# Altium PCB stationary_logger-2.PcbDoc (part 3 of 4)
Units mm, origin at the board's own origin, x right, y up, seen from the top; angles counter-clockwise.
Board outline 105 x 45 mm, 4 copper layers (Top Layer, Layer 2, Layer 3, Bottom Layer), stack 1.492 mm thick; 317 components, 187 nets, 816 pads, 302 vias.
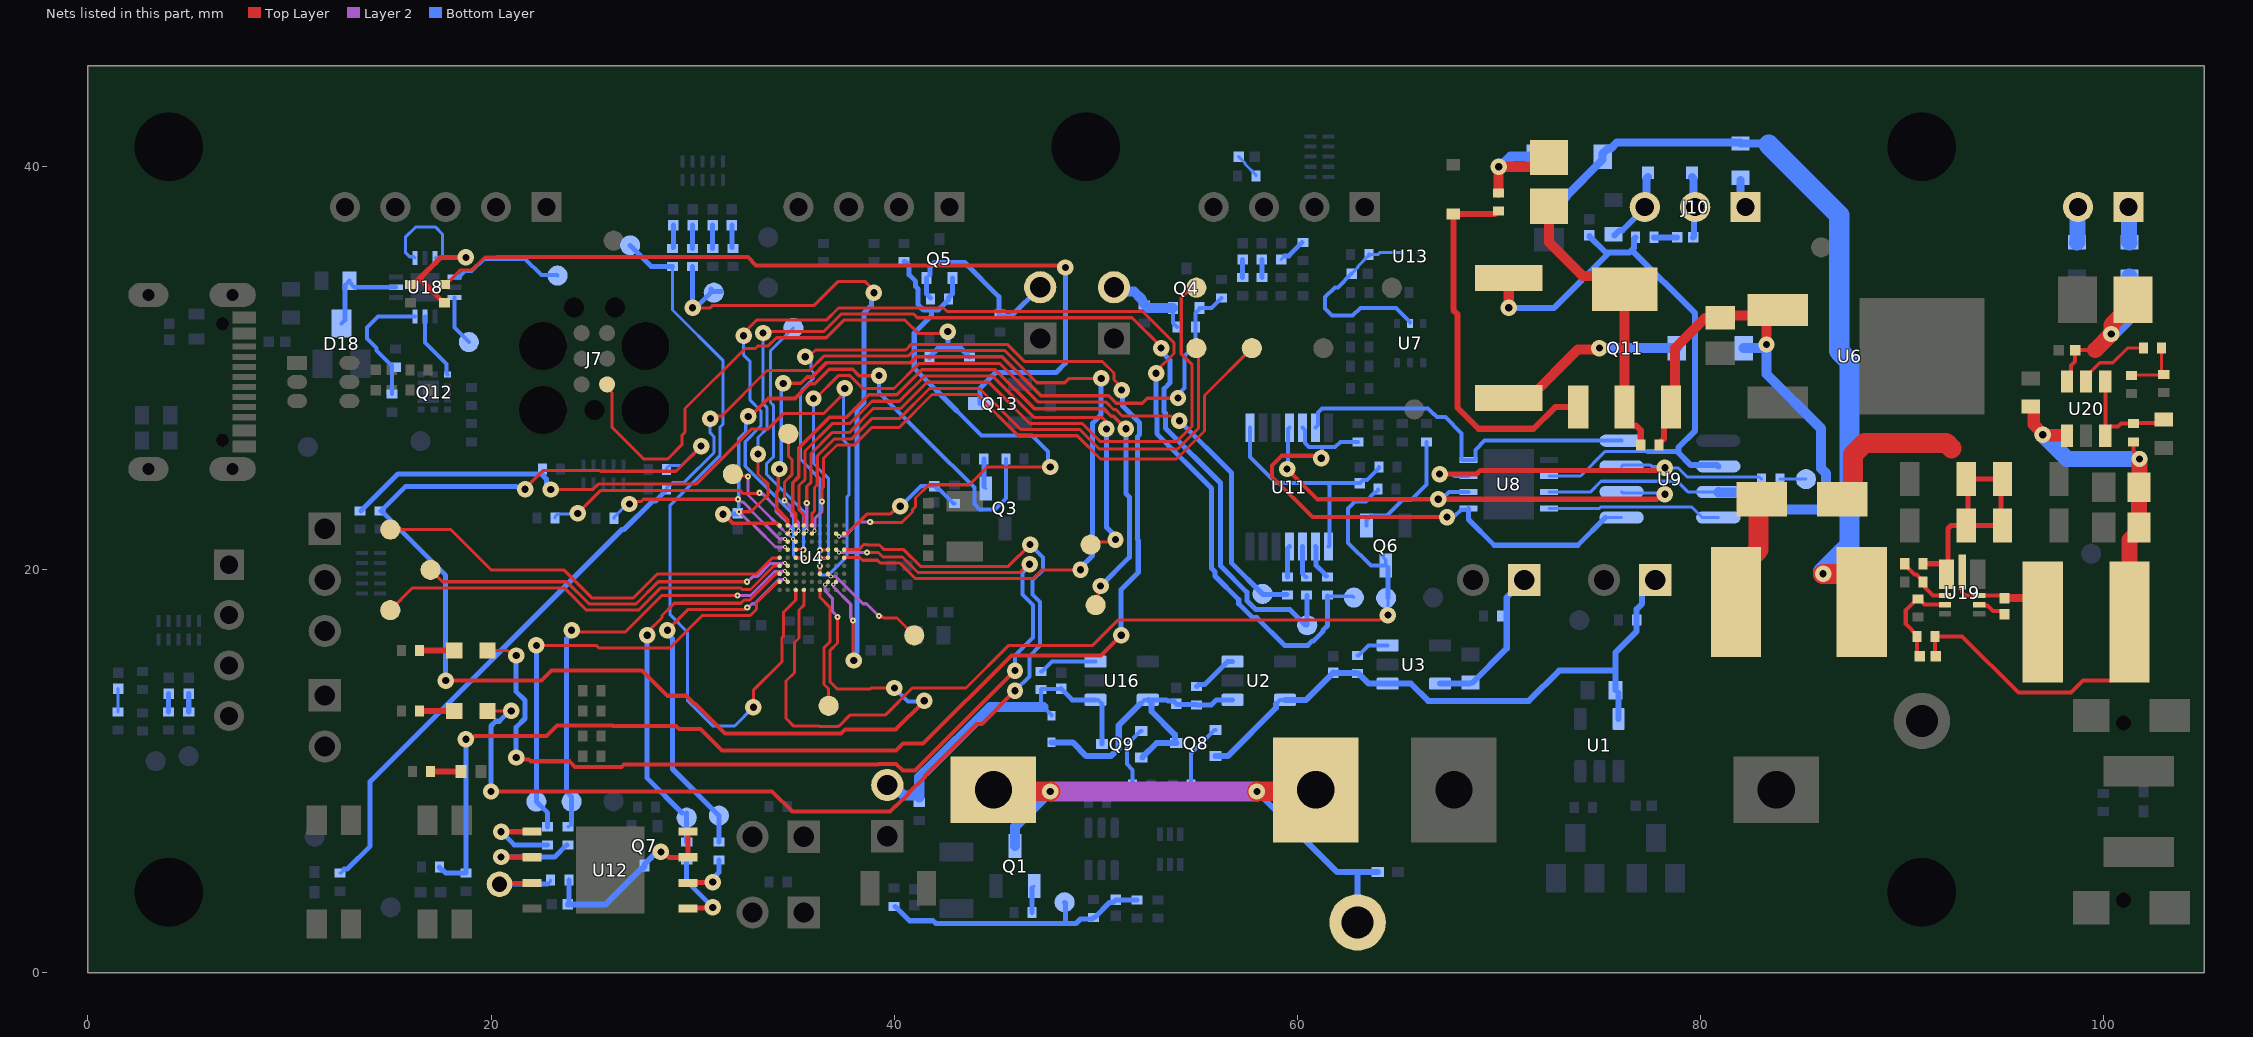
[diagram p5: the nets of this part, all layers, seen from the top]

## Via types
v1: diameter 0.813, hole 0.356, Top Layer to Bottom Layer, tented both sides, 238 vias
v2: diameter 0.305, hole 0.102, Top Layer to Layer 2, tented both sides, 29 vias
v3: diameter 0.203, hole 0.102, Top Layer to Layer 2, tented both sides, 27 vias
v4: diameter 0.305, hole 0.13, Top Layer to Bottom Layer, tented both sides, 8 vias

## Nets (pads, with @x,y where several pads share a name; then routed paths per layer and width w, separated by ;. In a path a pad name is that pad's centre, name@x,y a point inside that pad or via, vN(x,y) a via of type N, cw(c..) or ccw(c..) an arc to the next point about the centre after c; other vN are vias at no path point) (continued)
LED0: D13.A U4.D9 | length 53.3
  Top Layer w0.152: D13.A@19.825,13 v1(21,13) ; U4.D9@37.52,21 38.25,21 38.511,21.26 38.638,21.26 38.663,21.235 39.272,21.235 39.507,21 40.484,21 41.313,20.171 45.671,20.171 v1(46.75,21.25)
  Top Layer w0.2: v1(20,9) 33.947,9 34.947,8 39.796,8 40.064,8.268 40.098,8.268 40.714,8.884 40.714,8.918 41.523,9.727 41.523,9.801 44.081,12.359 44.359,12.359 v1(46,14)
  Bottom Layer w0.2: v1(46,14) 46.708,14.708 46.708,15.708 47.25,16.25 47.25,18.396 46.875,18.772 46.875,19.489 47.386,20 47.386,20.614 v1(46.75,21.25)
  Bottom Layer w0.25: v1(20,9) 20,12.25 20.234,12.484 20.411,12.484 20.927,13 v1(21,13)
LED1: D12.A U4.D8 | length 50.2
  Top Layer w0.152: D12.A@19.825,16 20.821,16 21.071,15.75 v1(21.25,15.75) ; v1(21.25,10.684) v1@21.358,10.576 ; 34.396,10.354 34.401,10.349 ; v2(38.663,20.854) 39.222,20.854 39.365,20.711 39.374,20.711 39.451,20.635 40.418,20.635 41.186,19.867 46.235,19.867 46.642,20.273 v1(46.727,20.273) ; v1@45.756,14.756 v1@45.776,14.756
  Top Layer w0.2: v1@21.358,10.576 21.885,10.576 21.961,10.5 23.893,10.5 24.171,10.223 26.473,10.223 26.599,10.349 34.401,10.349 39.202,10.349 39.226,10.373 40.098,10.373 40.438,10.032 41.032,10.032 v1@45.756,14.756 ; v1@45.776,14.756 46,14.98 v1(46,15)
  Layer 2 w0.152: v3@37.266,20.854 v2(38.663,20.854)
  Bottom Layer w0.2: v1(46,15) 46,15.75 46.885,16.635 46.885,18.263 46.372,18.776 46.372,19.849 46.727,20.205 v1(46.727,20.273)
  Bottom Layer w0.25: v1(21.25,10.684) 21.25,12.188 21.681,12.619 21.681,13.52 21.25,13.951 v1(21.25,15.75)
  other v3: 37.257,20.863
LIN.CS: R86.2 TP25.1 U4.E7 | length 41.2
  Top Layer w0.152: v1(36,28.5) 36.102,28.5 37.237,29.635 37.812,29.635 38.447,29 39.998,29 41.242,30.244 45.233,30.244 47.16,28.317 50.525,28.317 50.891,27.952 50.997,27.952 51.314,27.635 53.74,27.635 53.967,27.409 v1@54.145,27.409 ; v4(36.315,20.586) 36.322,20.593 36.713,20.593 U4.E7@36.72,20.6
  Bottom Layer w0.152: v1(36,28.5) 36,25.27 36.75,24.52 36.75,20.707 36.6,20.556 36.344,20.556 v4(36.315,20.586) ; TP25.1@58.282,18.8 TP25.1@58.307,18.775 ; R86.2@59.49,18.775 R86.2@59.515,18.75
  Bottom Layer w0.25: v1(54.156,27.399) 56.75,24.804 56.75,20.332 TP25.1@58.282,18.8 ; TP25.1@58.307,18.775 R86.2@59.49,18.775
LIN.DATA_IN: R67.2 TP29.1 U4.D2 | length 53.7
  Top Layer w0.152: v2(32.307,22.88) 32.9,22.88 33.306,23.287 33.326,23.287 33.75,23.711 33.75,24.25 33.25,24.75 v1(33.25,25.739) ; v1(33.5,31.75) 33.569,31.819 36.5,31.819 37.371,32.69 40.969,32.69 41.15,32.509 51.806,32.509 53.25,31.065 v1(53.25,31)
  Layer 2 w0.152: v2(32.307,22.88) 32.886,22.302 32.945,22.302 33.159,22.087 34.113,21.133 34.58,21.133 v3(34.583,21.137)
  Bottom Layer w0.152: v1(33.25,25.739) 33.25,26.564 33.703,27.017 33.703,28.034 33.5,28.237 v1(33.5,31.75) ; v1@53.25,30.872 v1(53.25,31) ; R67.2@60.465,18.75 R67.2@60.5,18.715
  Bottom Layer w0.25: v1@53.25,30.872 53.25,30.848 53.684,30.414 53.684,29.269 53.402,28.988 53.402,27.843 53.472,27.773 53.472,27.028 56.195,24.305 56.195,20.199 57.505,18.889 57.505,18.478 57.96,18.023 59.645,18.023 60.418,17.25 TP29.1@60.5,17.25 R67.2@60.5,18.715
LIN.DATA_OUT: R65.2 TP28.1 U4.E3 | length 59.9
  Top Layer w0.152: v1(32.535,31.617) 32.535,31.75 33.17,32.385 36.635,32.385 37.245,32.995 42.451,32.995 42.632,32.813 52.335,32.813 53.885,31.263 53.885,30.737 53,29.852 v1(53,29.75) ; U4.E3@35.12,20.6 35.126,20.594 35.521,20.594 v4(35.527,20.587)
  Bottom Layer w0.152: v1(32.535,31.617) 32.535,30.651 32.858,30.327 32.858,28.418 33.398,27.878 33.398,27.143 32.615,26.36 32.615,25.135 35,22.75 35,20.734 35.146,20.587 v4(35.527,20.587) ; R65.2@61.515,18.687 R65.2@61.515,18.75 61.578,18.687 62.752,18.687 TP28.1@62.815,18.625
  Bottom Layer w0.25: v1(53,29.75) 53,27.676 53.039,27.637 53.039,26.754 55.75,24.042 55.75,20.075 55.924,19.9 55.924,19.696 57.102,18.518 57.102,18.311 57.793,17.62 58,17.62 59.371,16.25 60.53,16.25 60.753,16.473 60.822,16.473 61.277,16.928 61.277,16.997 61.515,17.235 R65.2@61.515,18.687
LIN.nIS_PWRD: Q6.3 R69.2 TP30.1 U4.J4 | length 48.1
  Top Layer w0.152: U4.J4@35.52,19 35.52,18.244 35.285,18.009 35.285,16.617 35.056,16.388 35.056,14.899 34.635,14.478 34.635,12.634 35.029,12.241 36.298,12.241 36.322,12.217 37.178,12.217 37.202,12.24 37.263,12.24 37.827,12.805 39.581,12.805 40.909,14.133 43.571,14.133 45.689,16.25 49.852,16.25 51.102,17.5 64.081,17.5 64.331,17.75 v1(64.5,17.75)
  Bottom Layer w0.152: Q6.3@64.157,20.733 64.398,20.492 Q6.3@64.398,20.209 Q6.3@64.5,20.107 ; v1(64.5,17.75) TP30.1@64.5,18.6
  Bottom Layer w0.2: R69.2@64.009,23.994 64.009,23.944 63.89,23.825 63.84,23.825 63.41,23.395 62.88,23.395 62.526,23.041 62.526,21.34 63.656,20.209 Q6.3@64.398,20.209
  Bottom Layer w0.25: TP30.1@64.5,18.6 Q6.3@64.5,20.107
LIN_BUS: C5.1 R84.2 R85.2 U8.6 U9.6 | length 32.6
  Top Layer w0.5: v1(70.5,33) R84.2@70.5,34.475
  Bottom Layer w0.152: U8.6@72.5,24.65 74.067,24.65 75.294,25.876 77.376,25.876 ; U9.6@80.043,25.192 80.1,25.135 U9.6@80.9,25.135
  Bottom Layer w0.25: 77.376,25.876 78.912,25.876
  Bottom Layer w0.3: v1(70.5,33) 72.75,33 75.5,35.75 ; C5.1@74.5,36.56 74.5,36.55 75.3,35.75 75.5,35.75 ; R85.2@76.8,36.5 76.725,36.425 76.725,35.975 76.612,35.862 ; U9.6@80.9,25.135 80.843,25.192 80.043,25.192 79.54,25.192 78.912,25.821 78.912,25.876 78.912,26.069 79.75,26.907 79.75,32.725 76.612,35.862 ; 75.5,35.75 76.5,35.75 76.612,35.862
LIN_BUSC: D17.2 FB8.2 J10.2 | length 3.1
  Bottom Layer w0.3: FB8.2@79.65,36.5 79.7,36.55 79.7,37.95 J10.2@79.75,38
  Bottom Layer w0.4: D17.2@79.6,39.5 79.675,39.425 79.675,38.075 J10.2@79.75,38
LIN_CSHV: U8.2 U9.2 U11.11 | length 25.4
  Top Layer w0.152: v1@78.071,23.75 v1(78.25,23.75)
  Top Layer w0.2: v1(59.5,25) 61,23.5 v1(67,23.5)
  Top Layer w0.25: v1(67,23.5) 77.821,23.5 v1@78.071,23.75
  Bottom Layer w0.152: v1(67,23.5) v1@67.179,23.5 ; U9.2@76.1,23.865 76.158,23.807 78.193,23.807 v1(78.25,23.75)
  Bottom Layer w0.2: v1(59.5,25) 59.555,25.055 59.555,26.995 U11.11@59.61,27.05 ; v1@67.179,23.5 67.529,23.85 U8.2@68.5,23.85
LIN_RXD: R77.2 U8.1 U9.1 U11.12 | length 27.5
  Top Layer w0.2: v1(61.199,25.538) 61.081,25.655 60.779,25.655 60.775,25.659 59.227,25.659 58.75,25.182 58.75,24.617 60.758,22.609 67.427,22.609 v1(67.434,22.615)
  Bottom Layer w0.152: U9.1@75.3,22.595 U9.1@76.1,22.595
  Bottom Layer w0.2: U11.12@60.26,27.05 60.385,26.925 60.385,26.293 60.58,26.098 61.235,26.098 ; v1(61.199,25.538) 61.235,25.574 61.235,26.098 ; R77.2@63.015,26.35 62.142,26.35 61.89,26.098 61.235,26.098 ; v1(67.434,22.615) 67.461,22.643 67.793,22.643 68.15,23 68.45,23 U8.1@68.5,23.05
  Bottom Layer w0.25: U8.1@68.5,23.05 68.5,22.5 69.781,21.219 73.924,21.219 U9.1@75.3,22.595
LIN_TXD: U8.4 U9.4 U11.13 | length 18.4
  Bottom Layer w0.2: U11.13@60.91,27.05 61.035,27.175 61.035,27.807 61.23,28.002 64.498,28.002 64.5,28 66.5,28 66.773,27.727 66.798,27.727 66.946,27.58 67.352,27.58 68.159,26.773 68.159,25.5 68.209,25.45 U8.4@68.5,25.45 68.8,25.45 68.85,25.5 68.85,25.952 69.303,26.405 U9.4@76.1,26.405
LIN_VBATC: C1.1 D14.A F1.2 FB6.1 | length 39.2
  Top Layer w1: v1(86.1,19.8) 87.275,19.8 88.025,19.05 F1.2@88.025,18.4
  Bottom Layer w0.4: C1.1@72.5,38.125 72.83,38.455 72.88,38.505 73.317,38.505 75.16,40.348 75.16,40.652 75.417,40.91 75.57,40.91 75.86,41.2 FB6.1@82,41.2 ; FB6.1@82,41.15 83.35,41.15
  Bottom Layer w0.5: C1.1@72.83,38.455 73.267,38.455 73.317,38.505
  Bottom Layer w1: 83.4,41.1 86.9,37.6 86.9,30.85 87.4,30.35 87.4,21.2 86.1,19.9 v1(86.1,19.8)
LIN_VBB: C2.1 D16.A Q11.S R76.2 U6.1 U8.7 U9.7 | length 37.4
  Top Layer w0.3: R76.2@77.95,26.2 77.95,26.25 78.2,26.5 78.2,27.725 Q11.S@78.55,28.075 Q11.S@78.75,28.275 ; U6.1@83.29,32.328 83.587,32.625 U6.1@83.85,32.888
  Top Layer w0.5: Q11.S@78.75,28.275 78.75,31 80.25,32.5 C2.1@81,32.5 ; C2.1@81,32.625 U6.1@83.587,32.625 ; v1(83.29,31.181) U6.1@83.29,32.328
  Bottom Layer w0.152: U8.7@72.5,23.85 74.537,23.85 75.081,24.394 78.861,24.394 79.389,23.865 U9.7@80.9,23.865
  Bottom Layer w0.5: U9.7@80.9,23.865 80.919,23.846 81.904,23.846 82.75,23 85.957,23 86.25,23.293 86.25,24.773 86,25.023 86,27 83.29,29.71 v1@83.29,31 ; D16.A@82.16,31 v1@83.29,31 ; v1(83.29,31.181) v1@83.29,31
LIN_WAKEn: R64.1 U8.3 U9.3 | length 20.1
  Top Layer w0.152: v1@78.124,24.935 v1(78.25,25.061)
  Top Layer w0.25: v1(67.068,24.75) 68.903,24.75 69.088,24.935 77.822,24.935 77.841,24.953 78.105,24.953 v1@78.124,24.935
  Bottom Layer w0.152: U9.3@76.1,25.135 76.158,25.192 77.539,25.192 77.615,25.116 78.195,25.116 v1(78.25,25.061) 78.895,25.061 79.35,24.606 82.944,24.606 R64.1@83.05,24.5
  Bottom Layer w0.2: v1(67.068,24.75) 67.703,24.75 67.803,24.65 U8.3@68.5,24.65
M2M_5V_MID: C38.1 C39.1 C40.1 C41.2 L1.2 R100.1 R101.1 U20.1 | length 32
  Top Layer w0.2: C38.1@91.74,15.7 91.65,15.79 R100.1@91.65,16.7 93,16.7 95.8,13.9 98.4,13.9 99,14.5 100.4,14.5 101.3,15.4 L1.2@101.3,17.4 ; R101.1@101.5,26.35 101.5,25.9 101.8,25.6 v1(101.8,25.5)
  Top Layer w0.6: C41.2@96.4,28.1 96.5,28.1 96.55,28.05 96.55,27.208 97,26.758 v1(97,26.7) 97.025,26.675 98.2,26.675 U20.1@98.2,26.65
  Top Layer w0.8: L1.2@101.3,17.4 101.3,21.47 101.775,21.945 C40.1@101.775,22.1 C39.1@101.775,24.1 101.8,24.125 v1(101.8,25.5)
  Bottom Layer w0.8: v1(97,26.7) 98.2,25.5 v1(101.8,25.5)
M2M_5V_OUT: C37.+ C42.2 FB19.1 U20.6 | length 9.2
  Top Layer w0.2: U20.6@98.2,29.35 98.4,29.55 98.4,30.14 98.6,30.34 C42.2@98.6,30.9 99.6,30.9
  Top Layer w0.8: 99.6,30.9 v1(100.4,31.7) 100.4,32.15 101.475,33.225 C37.+@101.475,33.4
  Bottom Layer w0.8: v1(100.4,31.7) 100.4,31.703 101.3,32.603 FB19.1@101.3,34.55
M2M_BST: C28.2 U19.6 | length 1.4
  Top Layer w0.2: U19.6@93.847,18.275 93.882,18.24 94.26,18.24 94.54,17.96 94.94,17.96 C28.2@95.1,17.8
M2M_EN: R99.2 R102.1 U19.2 | length 2.8
  Top Layer w0.2: R99.2@90.15,20.3 90.15,20.25 90.475,19.925 90.479,19.925 90.629,19.775 90.725,19.775 91.05,19.45 R102.1@91.05,19.4 91.05,19.228 91.552,18.725 U19.2@92.152,18.725
M2M_FB: C38.2 R100.2 R104.1 U19.3 | length 4.9
  Top Layer w0.2: C38.2@90.86,15.7 90.75,15.81 R100.2@90.75,16.7 90.75,16.75 90.2,17.3 90.2,18 90.75,18.55 R104.1@90.8,18.55 90.85,18.55 91.125,18.275 U19.3@92.152,18.275
M2M_FLT: C43.2 R101.2 U20.3 U20.4 | length 5.8
  Top Layer w0.2: U20.3@100.1,26.65 U20.3@100.1,26.9 ; U20.4@100.1,29.35 U20.3@100.1,26.9 ; C43.2@103,27.45 102.825,27.275 101.525,27.275 R101.2@101.5,27.25 100.888,27.25 100.737,27.1 100.3,27.1 U20.3@100.1,26.9
M2M_ILIM: R103.1 R105.2 R106.1 | length 3.1
  Top Layer w0.152: R103.1@101.35,29.65 101.375,29.675 102.975,29.675 R106.1@103,29.7 102.9,29.8 R105.2@102.9,31
  Top Layer w0.2: R103.1@101.35,29.65 R103.1@101.4,29.65
MCU_BOOT0: R30.1 R31.1 U4.D7 | length 84.8
  Top Layer w0.152: v1(35.593,30.575) 35.772,30.575 36.102,30.905 40.573,30.905 40.853,31.184 45.623,31.184 46.478,30.328 50.345,30.328 50.91,29.763 50.91,29.434 51.291,29.053 v1(51.291,28.917) ; v4(36.317,20.973) 36.33,20.986 36.706,20.986 U4.D7@36.72,21
  Top Layer w0.2: v1(18.75,11.591) 18.867,11.708 19.132,11.708 19.174,11.75 22.75,11.75 23.277,12.277 26.03,12.277 26.057,12.25 29.171,12.25 29.319,12.102 30.398,12.102 31.47,11.03 40.098,11.03 40.446,11.377 41.446,11.377 45.818,15.75 50.27,15.75 v1(51.27,16.75)
  Bottom Layer w0.152: R31.1@18.7,4.95 R31.1@18.75,4.95 ; v1(35.593,30.575) 35.675,30.575 35.876,30.374 35.876,29.912 36,29.789 36,29.507 35.44,28.947 35.44,28.838 35.365,28.763 35.365,25.474 36.317,24.523 v4(36.317,20.973) ; 52.073,24.176 52.073,24.196
  Bottom Layer w0.25: R30.1@17.45,5.25 17.45,5.2 17.55,5.1 17.6,5.1 17.75,4.95 R31.1@18.7,4.95 ; R31.1@18.75,4.95 v1(18.75,11.591) ; v1(51.27,16.75) 51.27,19.02 52.115,19.865 52.115,21.463 52.073,21.505 52.073,24.176 52.073,26.606 52.184,26.717 52.184,27.283 51.332,28.135 51.332,28.876 v1(51.291,28.917)
MCU_DBG_UART_RX: R35.2 R38.2 U4.H7 | length 65.7
  Top Layer w0.152: v1(17.75,14.5) v1@17.754,14.504 ; v1(21.692,24) 21.692,24.041 22.573,24.922 25.404,24.922 25.435,24.89 29.181,24.89 v1(30.426,26.135) ; v2(37.193,17.654) 37.19,17.651 37.19,16.367 36.83,16.006 36.83,14.434 37.189,14.075 38.795,14.075 38.855,14.135 v1(40.013,14.135)
  Top Layer w0.2: v1@17.754,14.504 22.504,14.504 23,15 27.5,15 28.75,13.75 29.702,13.75 30.102,13.35 30.143,13.35 30.34,13.154 30.346,13.154 31.612,11.888 37.375,11.888 37.569,12.082 40.082,12.082 v1(41.5,13.5)
  Layer 2 w0.152: v3(36.583,19.263) 36.58,19.26 36.58,18.949 36.936,18.593 36.936,17.936 37.193,17.679 v2(37.193,17.654)
  Bottom Layer w0.152: R38.2@14.5,22.928 R38.2@14.55,22.928 ; v1@21.566,24.126 v1(21.692,24) ; R35.2@28.7,24.972 28.7,25.022 28.849,25.171 29.462,25.171 v1(30.426,26.135)
  Bottom Layer w0.2: v1(40.013,14.135) 40.694,13.454 41.454,13.454 v1(41.5,13.5)
  Bottom Layer w0.25: v1(17.75,14.5) 17.75,19.728 14.55,22.928 15.749,24.126 21.265,24.126 21.283,24.108 21.547,24.108 v1@21.566,24.126
MCU_DBG_UART_TX: R36.2 R40.2 U4.G6 | length 38.6
  Top Layer w0.152: v1(22.96,23.983) 22.961,23.982 25.054,23.982 25.322,24.25 30.181,24.25 32.911,26.98 33.732,26.98 34.502,27.75 36.5,27.75 37.374,28.624 37.374,28.646 37.549,28.821 v1(37.549,29) ; v4(36.315,20.181) 36.317,20.178 36.317,19.803 U4.G6@36.32,19.8
  Bottom Layer w0.152: R36.2@13.5,22.928 R36.2@13.55,22.928 ; 22.55,24.7 R40.2@22.55,24.75 ; v4(36.315,20.181) 36.315,19.75 36.75,19.75 37.673,20.673 37.673,23.14 37.673,23.632 37.761,23.72 37.761,26.153 37.5,26.415 37.5,28.951 v1(37.549,29)
  Bottom Layer w0.25: R36.2@13.55,22.928 15.372,24.75 R40.2@22.55,24.75 ; 22.55,24.7 22.755,24.495 22.755,24.145 22.917,23.983 v1(22.96,23.983)
MCU_nRST: R32.1 R42.1 U4.E9 | length 74.8
  Top Layer w0.152: v1(30.883,27.5) 31.01,27.626 31.435,27.626 33.694,29.885 35.801,29.885 36.516,30.6 40.7,30.6 40.979,30.879 45.496,30.879 47.093,29.283 48.473,29.283 48.691,29.5 v1(50.275,29.5) ; U4.E9@37.52,20.6 38.308,20.6 38.435,20.473 39.172,20.473 39.238,20.407 39.248,20.407 39.324,20.33 40.292,20.33 41.06,19.562 46.914,19.562 47.352,20 v1(49.25,20)
  Bottom Layer w0.152: R32.1@12.5,4.95 12.55,4.95 12.699,5.099 R32.1@12.699,5.149 ; R42.1@28.7,23.95 28.7,24.05 28.849,24.199 28.899,24.199 29.041,24.341 29.591,24.341 31.066,25.816 31.066,26.606 30.87,26.801 30.87,27.487 v1(30.883,27.5) ; v1(49.25,20) v1@49.25,20.083
  Bottom Layer w0.25: R32.1@12.699,5.149 12.862,5.149 14,6.286 14,9.5 26.5,22 26.602,22 28.009,23.407 28.157,23.407 R42.1@28.7,23.95 ; v1@49.25,20.083 49.25,20.105 49.851,20.706 49.851,27.278 50.275,27.702 v1(50.275,29.5)
MCU_SPI_FLASH.CIPO: R80.1 TP39.1 U4.G2 | length 21.9
  Top Layer w0.152: v1(24,17) 24.083,16.917 26.667,16.917 28.47,18.72 v2(32.234,18.72)
  Layer 2 w0.152: v2(32.234,18.72) 32.872,18.72 34.066,19.914 34.447,19.914 34.46,19.927 34.574,19.927 v3(34.583,19.937)
  Bottom Layer w0.152: R80.1@23.81,7.25 23.851,7.25 R80.1@24,7.399 ; v1@24,16.831 v1(24,17)
  Bottom Layer w0.25: R80.1@24,7.399 24,8.729 23.75,8.979 23.75,16.581 v1@24,16.831
MCU_SPI_FLASH.COPI: R81.1 TP40.1 U4.G1 | length 19.2
  Top Layer w0.152: v1(27.75,16.75) 27.75,16.895 28.483,17.628 28.483,17.733 29.089,18.339 32.392,18.339 32.556,18.503 32.833,18.503 34.116,19.786 34.306,19.786 U4.G1@34.32,19.8
  Bottom Layer w0.152: TP40.1@29.481,7.929 TP40.1@29.71,7.929
  Bottom Layer w0.25: v1(27.75,16.75) 27.75,9.66 TP40.1@29.481,7.929 ; R81.1@29.71,6.5 TP40.1@29.71,7.929
MCU_SPI_FLASH.nCS: R82.2 TP41.1 U4.H1 | length 22.9
  Top Layer w0.152: v1(22.25,16.25) 25.217,16.25 25.35,16.117 28.863,16.117 30.475,17.73 32.86,17.73 33.177,18.046 33.177,18.365 34.198,19.386 34.306,19.386 U4.H1@34.32,19.4
  Bottom Layer w0.25: v1(22.25,16.25) TP41.1@22.25,8.5 22.81,7.94 R82.2@22.81,7.25
MCU_SPI_FLASH.SCK: R79.1 TP38.1 U4.H2 | length 18.4
  Top Layer w0.152: v1(28.75,17) 29.785,18.035 32.585,18.035 32.672,18.122 v2(32.714,18.122)
  Layer 2 w0.152: v2(32.714,18.122) 32.755,18.122 32.947,18.314 33.075,18.314 34.269,19.508 34.447,19.508 34.466,19.527 34.574,19.527 v3(34.583,19.537)
  Bottom Layer w0.152: v1@28.75,16.831 v1(28.75,17)
  Bottom Layer w0.25: v1@28.75,16.831 29,16.581 29,10.11 TP38.1@31.31,7.8 R79.1@31.31,6.5
MCU_SWCLK: R39.2 U4.B2 | length 13.6
  Top Layer w0.152: v1(24.3,22.8) 25.445,23.945 32.344,23.945 32.496,23.793 33.293,23.793 v2(33.322,23.822) ; U4.B2@34.72,21.8 v3(34.857,21.937)
  Layer 2 w0.152: v2(33.322,23.822) 33.363,23.822 33.435,23.75 33.5,23.75 34.142,23.108 34.142,22.886 34.857,22.171 v3(34.857,21.937)
  Bottom Layer w0.152: R39.2@23.175,22.575 23.175,22.625 23.324,22.774 24.274,22.774 v1(24.3,22.8)
MCU_SWDIO: R37.2 U4.C2 | length 9.7
  Top Layer w0.152: v1(26.867,23.265) 26.994,23.391 27.47,23.391 27.579,23.5 v2(32.25,23.5)
  Layer 2 w0.152: v2(32.25,23.5) 32.291,23.5 32.428,23.363 32.507,23.363 32.847,23.024 32.847,22.988 34.294,21.54 34.58,21.54 v3(34.583,21.537)
  Bottom Layer w0.152: R37.2@26.102,22.56 26.102,22.61 26.757,23.265 v1(26.867,23.265)
nDB: R26.1 R27.2 U18.10 U18.12 | length 11.3
  Top Layer w0.25: R27.2@16,34.05 16.05,34.05 16.4,34.4 ; R26.1@17.7,33.25 17.65,33.25 16.5,34.4 16.4,34.4 ; v1(18.75,35.5) 17.5,35.5 16.4,34.4
  Bottom Layer w0.152: U18.10@16.23,35.47 16.23,35.485 16.181,35.534 15.966,35.534 15.75,35.75 15.75,36.5 16.25,37 17.25,37 17.584,36.666 17.584,35.559 ; U18.12@17.23,35.47 17.279,35.5 v1(18.75,35.5)
NetC4_2: C4.2 D7.A J2.2 Q9.D R3.1 R12.2 U16.1 | length 17.3
  Bottom Layer w0.2: D7.A@47.8,12.76 47.8,12.8 47.291,13.309 R3.1@47.291,14.05 47.316,14.075 48.266,14.075 C4.2@48.291,14.1 ; U16.1@49.991,13.55 50.116,13.55 U16.1@50.316,13.35
  Bottom Layer w0.25: C4.2@48.291,14.1 48.841,13.55 U16.1@49.991,13.55 ; Q9.D@50.316,11.346 U16.1@50.316,13.35
  Bottom Layer w0.5: J2.2@39.662,9.32 39.959,9.32 40.48,8.8 41.15,8.8 41.25,8.7 41.25,9.707 41.543,10 41.575,10 44.766,13.191 47.409,13.191
NetC6_1: C6.1 D18.3 U18.8 | length 4.7
  Bottom Layer w0.2: D18.3@12.58,32.22 D18.3@12.75,32.39 ; C6.1@12.75,34.115 C6.1@12.98,34.345 ; C6.1@12.98,34.27 13.23,34.02 U18.8@15.28,34.02
  Bottom Layer w0.25: D18.3@12.75,32.39 C6.1@12.75,34.115
NetC10_1: C10.1 C14.2 J16.1 Q8.S R1.1 R11.1 U1.5 U2.5 U3.1 | length 30.7
  Bottom Layer w0.2: U2.5@58.95,13.35 59.15,13.55 U2.5@59.4,13.55 ; C14.2@61.8,14.9 C14.2@61.825,14.875 ; R11.1@62.975,14.875 R11.1@63,14.85 R11.1@63.05,14.85 ; C10.1@75.8,14.025 C10.1@75.95,13.875
  Bottom Layer w0.3: Q8.S@55.95,10.75 56.55,10.75 58.95,13.15 U2.5@58.95,13.35 ; U2.5@59.4,13.55 60.45,13.55 C14.2@61.8,14.9 ; C14.2@61.825,14.875 R11.1@62.975,14.875 ; R11.1@63.05,14.85 63.55,14.35 U3.1@64.491,14.35 65.65,14.35 66.5,13.5 71.5,13.5 73,15 75.8,15 ; C10.1@75.8,14.025 75.8,15 ; U1.5@75.95,12.6 C10.1@75.95,13.875 ; J16.1@77.77,19.5 77.12,18.85 77.12,18.32 76.85,18.05 R1.1@76.85,17.5 76.85,16.95 75.8,15.9 75.8,15
NetC13_2: C13.2 D7.K Q8.D Q9.S R10.1 U2.1 U16.5 | length 16.1
  Bottom Layer w0.2: U16.5@52.216,13.35 52.416,13.55 U16.5@52.591,13.55 ; Q9.S@52.266,10.696 Q9.S@52.316,10.696 ; Q8.D@53.95,11.4 Q8.D@54,11.4
  Bottom Layer w0.25: U16.5@52.591,13.55 52.624,13.55 53.516,13.55 53.581,13.485 53.865,13.485 C13.2@54,13.35 54.025,13.325 54.975,13.325 R10.1@55,13.3 55.75,13.3 56,13.55 U2.1@56.8,13.55
  Bottom Layer w0.3: D7.K@47.8,11.44 48.855,11.44 49.545,10.75 50.75,10.75 51.148,11.148 51.148,12.282 U16.5@52.216,13.35 ; Q9.S@52.316,10.696 53.02,11.4 Q8.D@53.95,11.4 ; U16.5@52.624,13.55 52.774,13.4 52.774,12.976 53.933,11.817 53.933,11.467 Q8.D@54,11.4
NetC15_1: C15.1 J3.1 R13.1 U3.5 | length 7.8
  Bottom Layer w0.2: C15.1@68.55,14.35 C15.1@68.6,14.4 C15.1@68.7,14.4
  Bottom Layer w0.3: U3.5@67.091,14.35 C15.1@68.55,14.35 ; C15.1@68.7,14.4 70.4,16.1 70.4,17.7 70.4,18.63 J3.1@71.27,19.5
NetC24_2: C24.2 R29.1 U4.B9 | length 6.8
  Top Layer w0.152: U4.B9@37.52,21.8 37.529,21.809 37.688,21.809 38.638,22.759 39.802,22.759 40.201,23.157 v1(40.302,23.157)
  Bottom Layer w0.2: v1(40.302,23.157) 40.339,23.157 41.332,24.15 C24.2@42,24.15 42.16,23.99 42.26,23.99 42.95,23.3 R29.1@43,23.3
NetC25_2: C25.2 R28.1 U4.A1 | length 28.6
  Top Layer w0.178: v1(31.51,22.76) 31.546,22.76 32.004,22.302 34.205,22.302 34.307,22.2 U4.A1@34.32,22.2 ; v1(32.763,27.615) 32.878,27.615 33.763,28.5 35.084,28.5 35.81,29.226 36.06,29.226 36.787,29.953 37.943,29.953 38.261,29.635 v1(39.25,29.635)
  Bottom Layer w0.178: C25.2@32.225,22.775 C25.2@32.25,22.8 32.297,22.848 32.297,26.492 32.642,26.836 32.642,27.493 v1(32.763,27.615)
  Bottom Layer w0.2: v1(39.25,29.635) 39.25,28.807 41.68,26.377 43.98,24.077 43.98,23.27 44.25,23 45,23 45.55,23.55 R28.1@45.55,25.5
  Bottom Layer w0.25: v1(31.51,22.76) 31.53,22.78 32.22,22.78 C25.2@32.225,22.775
NetC28_1: C28.1 L1.1 U19.7 U19.9 | length 5.8
  Top Layer w0.2: U19.9@93,19.89 93,18.9 93.175,18.725 U19.7@93.847,18.725 94.975,18.725 C28.1@95.1,18.6 ; L1.1@96.1,18.6 97,17.7 L1.1@97,17.4
  Top Layer w0.4: C28.1@95.1,18.6 L1.1@96.1,18.6
NetC29_2: C29.2 R50.2 U7.5 U13.B1 | length 10.3
  Bottom Layer w0.152: C29.2@62.707,34.7 63.018,35.012 63.018,35.062 R50.2@63.557,35.601 ; R50.2@63.557,35.651 64.026,35.651 64.125,35.75 U13.B1@65.207,35.75 ; U7.5@65.607,32.225 U7.5@65.607,32.3
  Bottom Layer w0.2: C29.2@62.707,34.7 62.021,34.015 61.867,34.015 61.377,33.525 61.377,32.975 61.737,32.615 62.756,32.615 63.141,33 64.907,33 U7.5@65.607,32.3 ; R50.2@63.557,35.601 R50.2@63.557,35.651
NetC30_2: C30.2 C31.2 C32.2 C36.2 D10.K R99.1 U19.1 | length 20.2
  Top Layer w0.25: R99.1@91.05,20.3 91.978,20.3 U19.1@92.3,19.978 ; U19.1@92.3,19.822 U19.1@92.3,19.978 ; C31.2@93.275,24.5 94.925,24.5 94.925,22.2 C30.2@93.294,22.2 ; C30.2@93.294,22.182 C30.2@93.294,22.2 ; C31.2@93.294,24.482 C30.2@93.294,22.2 ; U19.1@92.3,19.978 92.3,22.054 92.446,22.2 C30.2@93.294,22.2
  Top Layer w1: D10.K@87.2,23.5 87.575,23.875 87.575,25.714 88.161,26.3 92.2,26.3 92.469,26.031
NetC33_2: C33.2 R63.1 U11.1 U11.8 | length 12
  Bottom Layer w0.2: U11.8@57.66,27.05 57.66,25.59 58.95,24.3 61.5,24.3 ; U11.1@61.56,21.15 61.603,21.193 61.603,24.197 61.5,24.3 ; R63.1@64.065,25.1 64.065,25.05 63.475,24.46 63.27,24.46 C33.2@63.11,24.3 61.5,24.3
NetC35_2: C35.2 Q7.D R78.2 U12.7 U12.8 | length 9.7
  Top Layer w0.25: v1(28.426,6) 28.579,6 28.844,5.735 U12.7@29.78,5.735 U12.8@29.78,7.005
  Bottom Layer w0.152: C35.2@23.81,3.4 C35.2@23.86,3.45 ; Q7.D@27.61,5.325 Q7.D@27.61,5.375
  Bottom Layer w0.25: C35.2@23.86,3.45 R78.2@23.86,4.6
  Bottom Layer w0.3: C35.2@23.81,3.4 25.685,3.4 27.46,5.175 27.51,5.175 27.61,5.275 Q7.D@27.61,5.325 ; Q7.D@27.61,5.375 28.137,5.902 28.328,5.902 v1(28.426,6)
NetD3_2: D3.2 J4.1 Q1.3 TP12.1 | length 29.5
  Top Layer w1: J4.1@44.929,9.08 v1(47.75,9) ; v1(58,9) J4.1@60.929,9.08
  Layer 2 w1: v1@47.83,9 v1(58,9)
  Bottom Layer w0.3: v1(58,9) 62,5 62.975,5 ; TP12.1@63,2.5 63,4.975 62.975,5 ; D3.2@64,5 62.975,5
  Bottom Layer w0.5: Q1.3@46,6.291 46.009,6.3 46.009,7.259 v1(47.75,9)
NetD9_1: D9.1 J7.1 R34.2 | length 26.9
  Top Layer w0.152: J7.1@25.762,29.203 25.762,29.028 26,28.79 26,27.071 27.571,25.5 28.763,25.5 29.486,26.223 29.486,26.69 29.626,26.83 29.626,28.003 32.608,30.985 33.122,30.985 33.25,31.113 33.764,31.113 34.166,31.515 36.627,31.515 37.497,32.385 40.545,32.385 41.198,31.732 42.579,31.732 v1(42.666,31.819)
  Bottom Layer w0.25: D9.1@41.75,30.5 41.75,30.55 42.204,31.004 42.6,31.004 ; v1(42.666,31.819) 42.666,31.07 42.6,31.004 ; R34.2@43.75,30.55 43.296,31.004 42.6,31.004
NetD10_A: D10.A F1.1 | length 5.6
  Top Layer w1: F1.1@81.775,18.4 81.775,19.875 82.9,21 D10.A@82.9,23.5
NetD11_K: D11.K R116.2 | length 1.5
  Top Layer w0.3: R116.2@17,10 D11.K@18.5,10
NetD12_K: D12.K R44.2 | length 1.7
  Top Layer w0.3: R44.2@16.45,16 D12.K@18.175,16
NetD13_K: D13.K R46.2 | length 1.7
  Top Layer w0.3: R46.2@16.45,13 D13.K@18.175,13
NetD14_K: D14.K R74.1 R75.2 | length 6
  Top Layer w0.5: R74.1@70,38.7 v1(70,40) 72.04,40 R75.2@72.5,40.46
  Bottom Layer w0.5: v1(70,40) 70.085,40 70.585,40.5 D14.K@71.84,40.5
NetD15_K: D15.K Q11.G R74.2 | length 18.9
  Top Layer w0.3: R74.2@70,37.8 69.95,37.8 69.808,37.658 D15.K@67.75,37.658 67.75,32.889 67.956,32.683 67.956,28.044 69,27 71.728,27 72.803,28.075 Q11.G@73.95,28.075
NetD16_K: D16.K R84.1 | length 10.4
  Top Layer w0.5: R84.1@69.475,28.525 R84.1@70.5,28.525 71.525,28.525 73.94,30.94 74.94,30.94 v1(75,31)
  Bottom Layer w0.5: v1(75,31) D16.K@78.84,31
NetD17_1: D17.1 FB7.2 J10.3 | length 3.7
  Bottom Layer w0.3: FB7.2@75.75,36.6 75.988,36.838 76.135,36.838 77.25,37.952 J10.3@77.25,38
  Bottom Layer w0.4: J10.3@77.25,38 77.325,38.075 77.325,39.425 D17.1@77.4,39.5
NetFB3_1: FB3.1 R59.2 | length 1.5
  Bottom Layer w0.152: FB3.1@59.2,35.397 FB3.1@59.384,35.581 ; R59.2@60.25,36.247 R59.2@60.3,36.247
  Bottom Layer w0.25: FB3.1@59.384,35.581 59.584,35.581 R59.2@60.25,36.247
NetFB4_1: FB4.1 R61.2 | length 0.9
  Bottom Layer w0.25: R61.2@58.25,34.497 FB4.1@58.25,35.397
NetFB5_1: FB5.1 R62.2 | length 0.9
  Bottom Layer w0.25: R62.2@57.3,34.497 FB5.1@57.3,35.397
NetFB6_2: FB6.2 J10.1 | length 1.5
  Bottom Layer w0.4: FB6.2@82,39.35 82,38.25 J10.1@82.25,38
NetFB8_1: FB8.1 R85.1 | length 1.2
  Bottom Layer w0.3: R85.1@77.7,36.5 FB8.1@78.85,36.5
NetFB11_1: FB11.1 R87.2 | length 1.3
  Bottom Layer w0.152: FB11.1@57.1,40.5 57.411,40.189 57.411,40.138 57.95,39.6 R87.2@57.95,39.55
NetFB12_1: FB12.1 R88.2 | length 1.2
  Bottom Layer w0.152: R88.2@31.95,36 R88.2@32,35.95
  Bottom Layer w0.25: R88.2@31.95,36 FB12.1@31.95,37.1
NetFB13_1: FB13.1 R89.2 | length 1.2
  Bottom Layer w0.25: R89.2@31,35.95 FB13.1@31,37.1
NetFB14_1: FB14.1 R90.2 | length 1.2
  Bottom Layer w0.152: R90.2@1.5,12.95 FB14.1@1.5,14.1
NetFB15_1: FB15.1 R93.2 | length 0.9
  Bottom Layer w0.25: R93.2@4,12.95 FB15.1@4,13.85
NetFB16_1: FB16.1 R94.2 | length 0.9
  Bottom Layer w0.25: R94.2@5,12.95 FB16.1@5,13.85
NetFB17_1: FB17.1 R66.2 | length 1.2
  Bottom Layer w0.25: R66.2@30,35.95 FB17.1@30,37.1
NetFB18_1: FB18.1 R68.2 | length 1.2
  Bottom Layer w0.152: R68.2@29,35.95 R68.2@29.05,36
  Bottom Layer w0.25: R68.2@29.05,36 FB18.1@29.05,37.1
NetFB19_2: FB19.2 J19.1 | length 1.8
  Bottom Layer w0.8: J19.1@101.25,38 101.275,37.975 101.275,36.275 FB19.2@101.3,36.25
NetFB20_2: FB20.2 J19.2 | length 1.8
  Bottom Layer w0.8: FB20.2@98.7,36.25 98.725,36.275 98.725,37.975 J19.2@98.75,38
NetJ9_2: J9.2 Q4.S R45.2 R47.1 | length 4.2
  Bottom Layer w0.2: Q4.S@53.85,32.997 53.85,32.246 R47.1@54.05,32.046
  Bottom Layer w0.5: J9.2@50.912,34.02 51.122,33.81 51.899,33.81 52.312,33.397 ; R45.2@52.4,33.2 52.603,32.997 Q4.S@53.85,32.997
NetJ11_2: J11.2 Q5.S R54.2 R56.1 | length 9.5
  Bottom Layer w0.152: Q5.S@41.6,34.472 Q5.S@41.774,34.646 ; R56.1@41.8,33.447 R56.1@41.8,33.497
  Bottom Layer w0.25: Q5.S@41.6,34.472 41.6,33.697 R56.1@41.8,33.497 ; Q5.S@41.774,34.646 41.774,35.024 42,35.25 43.5,35.25 45.2,33.55 45.2,32.6 45.83,32.6 J11.2@47.25,34.02
NetQ1_1: Q1.1 R14.1 | length 1.4
  Bottom Layer w0.152: Q1.1@46.85,4.209 Q1.1@46.95,4.309
  Bottom Layer w0.25: R14.1@46.85,3 Q1.1@46.85,4.209
NetQ3_1: Q3.1 R25.2 | length 1.5
  Bottom Layer w0.152: Q3.1@44.45,24.133 Q3.1@44.55,24.033
  Bottom Layer w0.25: Q3.1@44.45,24.133 R25.2@44.45,25.5
NetQ6_1: Q6.1 R70.1 | length 6.1
  Bottom Layer w0.2: Q6.1@63.448,22.191 63.448,22.473 63.665,22.691 64.463,22.691 65.231,23.459 65.641,23.459 66.409,24.227 66.409,26.34 R70.1@66.419,26.35
NetQ8_G: Q8.G R2.1 | length 3.3
  Bottom Layer w0.2: R2.1@54.741,9.316 54.741,10.891 55.9,12.05 Q8.G@55.95,12.05
NetQ9_G: Q9.G R118.1 | length 3.1
  Bottom Layer w0.2: R118.1@51.841,9.316 51.841,10.075 51.55,10.366 51.55,11.33 52.216,11.996 Q9.G@52.266,11.996
NetQ11_D: Q11.D R75.1 R76.1 | length 14.7
  Top Layer w0.3: Q11.D@76.25,28.075 76.25,27.5 76.6,27.15 76.825,27.15 77.05,26.925 R76.1@77.05,26.2
  Top Layer w0.5: R75.1@72.5,38.04 72.5,36.25 74.168,34.582 75.593,34.582 Q11.D@76.25,33.925 Q11.D@76.25,28.052
NetQ12_G: Q12.G U18.5 | length 3.3
  Bottom Layer w0.2: U18.5@16.73,32.57 16.73,31.283 17.791,30.222 17.791,29.736 Q12.G@17.832,29.695
NetQ13_3: Q13.3 R26.2 | length 41.8
  Top Layer w0.152: R26.2@17.7,34.15 17.75,34.15 18.467,34.867 19.063,34.867 19.705,35.51 20.3,35.51
  Top Layer w0.2: 20.3,35.51 32.742,35.51 33.15,35.102 48.398,35.102 v1(48.5,35)
  Bottom Layer w0.25: Q13.3@44.259,28.25 44.259,29.009 45.045,29.795 48.045,29.795 48.5,30.25 v1(48.5,35)
NetR3_2: R3.2 U16.3 | length 2.9
  Bottom Layer w0.2: R3.2@47.291,14.95 47.341,14.95 47.841,15.45 U16.3@49.991,15.45
NetR10_2: R10.2 U2.3 | length 2.4
  Bottom Layer w0.2: R10.2@55,14.2 R10.2@55.05,14.2
  Bottom Layer w0.25: R10.2@55,14.2 55.1,14.3 55.4,14.3 56.55,15.45 U2.3@56.8,15.45
NetR11_2: R11.2 U3.3 | length 1.7
  Bottom Layer w0.2: R11.2@63,15.75 63.05,15.75 63.55,16.25 U3.3@64.491,16.25
NetR64_2: R64.2 TP26.1 | length 1.3
  Bottom Layer w0.152: R64.2@83.95,24.5 TP26.1@85.25,24.5
NetR65_1: R65.1 U11.2 | length 1.7
  Bottom Layer w0.25: U11.2@60.91,21.15 60.94,21.12 60.94,20.225 61.365,19.8 61.365,19.75 61.415,19.7 R65.1@61.465,19.7
NetR67_1: R67.1 U11.3 | length 1.6
  Bottom Layer w0.2: R67.1@60.26,19.805 60.415,19.65 R67.1@60.465,19.65
  Bottom Layer w0.25: R67.1@60.26,19.805 U11.3@60.26,21.15
NetR78_1: R78.1 TP23.1 U12.3 | length 4.3
  Top Layer w0.152: TP23.1@20.41,4.4 TP23.1@20.443,4.432 ; U12.3@22.008,4.432 U12.3@22.04,4.465
  Top Layer w0.25: TP23.1@20.443,4.432 U12.3@22.008,4.432
  Bottom Layer w0.152: TP23.1@20.41,4.4 TP23.1@20.411,4.401 ; R78.1@22.811,4.401 22.96,4.55 R78.1@22.96,4.6
  Bottom Layer w0.25: TP23.1@20.411,4.401 R78.1@22.811,4.401
NetR79_2: R79.2 U12.6 | length 2.5
  Top Layer w0.152: U12.6@29.78,4.465 U12.6@29.798,4.483 ; v1@30.982,4.483 v1(31,4.5)
  Top Layer w0.25: U12.6@29.798,4.483 v1@30.982,4.483
  Bottom Layer w0.152: v1(31,4.5) v1@31,4.679
  Bottom Layer w0.25: v1@31,4.679 31.31,4.989 R79.2@31.31,5.6
NetR80_2: R80.2 U12.2 | length 5.1
  Top Layer w0.152: v1(20.5,5.75) v1@20.508,5.743 ; U12.2@22.033,5.743 U12.2@22.04,5.735
  Top Layer w0.25: v1@20.508,5.743 U12.2@22.033,5.743
  Bottom Layer w0.152: R80.2@23.76,6.35 R80.2@23.81,6.35
  Bottom Layer w0.25: v1(20.5,5.75) 23.16,5.75 R80.2@23.76,6.35
NetR81_2: R81.2 U12.5 | length 4.1
  Top Layer w0.152: U12.5@29.78,3.195 U12.5@29.808,3.223 ; v1@30.972,3.223 v1(31,3.25)
  Top Layer w0.25: U12.5@29.808,3.223 v1@30.972,3.223
  Bottom Layer w0.25: R81.2@29.71,5.6 29.71,4.54 v1(31,3.25)
NetR82_1: R82.1 U12.1 | length 4.1
  Top Layer w0.152: v1(20.5,7) v1@20.502,7.003 ; U12.1@22.038,7.003 U12.1@22.04,7.005
  Top Layer w0.25: v1@20.502,7.003 U12.1@22.038,7.003
  Bottom Layer w0.25: v1(20.5,7) 21.15,6.35 R82.1@22.81,6.35
NetR86_1: R86.1 U11.4 | length 1.5
  Bottom Layer w0.25: R86.1@59.515,19.65 59.515,21.055 U11.4@59.61,21.15
NetR95_1: R95.1 R96.2 U18.6 | length 6.5
  Bottom Layer w0.2: R95.1@15.08,28.717 15.08,30.17 15.03,30.17 14.324,30.876 14.324,30.994 13.841,31.477 13.841,32.023 14.388,32.57 U18.6@16.23,32.57
NetR105_1: R105.1 U20.5 | length 3.7
  Top Layer w0.152: U20.5@99.15,29.35 99.15,29.6 99.824,30.274 100.474,30.274 101.201,31 R105.1@102,31
NetTP10_1: TP10.1 U4.A3 | length 32.6
  Top Layer w0.178: U4.A3@35.12,22.2 35.12,22.78 34.967,22.932 34.967,23.14 34.967,24.313 35.26,24.605 35.26,26.03 36.796,27.567 37.635,27.567 38.75,28.683 40.129,28.683 41.373,29.927 45.022,29.927 46.949,28 50.394,28 50.782,27.612 50.888,27.612 v1(51.5,27) ; TP10.1@50,18.25 50.129,18.379 50.129,19.078 v1(50.25,19.199)
  Bottom Layer w0.25: v1(50.25,19.199) 51.67,20.619 51.67,23.616 51.5,23.786 v1(51.5,27)
NetTP13_1: TP13.1 U4.G7 | length 5.5
  Top Layer w0.152: U4.G7@36.72,19.8 v3(36.857,19.663) ; v2(39.25,17.699) 39.279,17.67 39.422,17.67 39.482,17.61 40.14,17.61 TP13.1@41,16.75
  Layer 2 w0.152: v3@36.87,19.663 36.875,19.659 37.115,19.659 38.46,18.314 38.634,18.314 v2@39.249,17.699
NetTP16_1: TP16.1 U4.J6 | length 6.2
  Top Layer w0.152: U4.J6@36.32,19 36.32,18.634 36.812,18.142 36.812,16.419 36.525,16.132 36.525,14.308 36.75,14.082 TP16.1@36.75,13.25
NetTP18_1: TP18.1 U18.3 | length 2.5
  Bottom Layer w0.2: U18.3@18.18,33.52 18.18,32.02 TP18.1@18.9,31.3
NetTP19_1: TP19.1 U4.F1 | length 21.2
  Top Layer w0.152: TP19.1@15,18 16.101,19.101 23.638,19.101 24.74,18 27.319,18 28.42,19.101 32.387,19.101 32.463,19.025 32.872,19.025 34.033,20.186 34.306,20.186 U4.F1@34.32,20.2
NetTP27_1: TP27.1 U18.1 | length 5.8
  Bottom Layer w0.2: U18.1@18.405,34.52 18.704,34.819 19.032,34.819 19.645,35.431 21.694,35.431 22.5,34.625 23.275,34.625 TP27.1@23.3,34.6
  Bottom Layer w0.25: U18.1@18.18,34.52 U18.1@18.405,34.52
NetTP33_1: TP33.1 U4.B5 | length 31.2
  Top Layer w0.152: U4.B5@35.92,21.8 v3(36.057,21.937) ; v2(36.428,23.394) 36.428,24.032 36.491,24.095 36.491,25.52 37.167,26.195 38.025,26.195 38.89,27.06 40.249,27.06 41.884,28.695 44.116,28.695 46.158,26.653 48,26.653 48.001,26.652 49.088,26.652 50.24,25.5 54.017,25.5 55.4,26.883 55.4,28.65 TP33.1@57.75,31
  Layer 2 w0.152: v3(36.057,21.937) 36.057,22.108 36.072,22.124 36.072,22.556 36.428,22.911 v2(36.428,23.394)
NetTP34_1: TP34.1 U4.A5 | length 29.5
  Top Layer w0.152: U4.A5@35.92,22.2 35.92,22.784 36.047,22.911 36.047,24.082 36.187,24.221 36.187,25.646 37.04,26.5 37.899,26.5 38.899,27.5 40.258,27.5 41.757,29 44.243,29 45.242,28 45.25,28 46.292,26.958 49.213,26.958 50.171,26 54.086,26 55.095,27.009 55.095,30.905 TP34.1@55,31
NetTP43_1: TP43.1 U4.F2 | length 19.1
  Top Layer w0.152: TP43.1@17,20 17.594,19.406 23.765,19.406 24.866,18.305 27.193,18.305 28.294,19.406 v2(32.694,19.406)
  Layer 2 w0.152: v2(32.694,19.406) 32.725,19.406 32.979,19.66 33.202,19.66 33.863,20.321 34.447,20.321 34.453,20.327 34.574,20.327 v3(34.583,20.337)
NetTP44_1: TP44.1 U4.E1 | length 21.5
  Top Layer w0.152: TP44.1@15,22 18,22 20,20 23.602,20 24.992,18.61 27.066,18.61 28.244,19.787 33.151,19.787 33.95,20.586 34.306,20.586 U4.E1@34.32,20.6
NetTP45_1: TP45.1 U4.D3 | length 12.8
  Top Layer w0.152: U4.D3@35.12,21 35.123,20.997 35.499,20.997 v4(35.502,20.994)
  Bottom Layer w0.152: TP45.1@35,32 33.865,30.865 33.865,28.303 34.008,28.16 34.008,25.599 33.672,25.263 33.672,24.737 35.502,22.907 v4(35.502,20.994)
NetTP46_1: TP46.1 U4.C3 | length 5
  Top Layer w0.152: TP46.1@32,24.75 32.09,24.66 32.721,24.66 v2(32.75,24.631) ; v3(34.983,21.537) U4.C3@35.12,21.4
  Layer 2 w0.102: 34.479,21.982 34.759,21.702 34.804,21.702 34.97,21.537 v3(34.983,21.537)
  Layer 2 w0.152: v2(32.75,24.631) 32.75,23.711 33.321,23.14 34.479,21.982
NetTP47_1: TP47.1 U4.B3 | length 5.5
  Top Layer w0.152: v2(34.561,23.445) 34.561,24.356 34.942,24.737 34.942,25.452 34.75,25.644 TP47.1@34.75,26.75 ; U4.B3@35.12,21.8 v3(35.257,21.937)
  Layer 2 w0.152: v2(34.561,23.445) 34.904,23.102 34.904,22.708 35.26,22.353 35.26,21.94 v3(35.257,21.937)
NetTP49_1: TP49.1 U4.A4 | length 28.7
  Top Layer w0.152: U4.A4@35.52,22.2 35.52,22.73 35.285,22.965 35.285,23.14 35.285,24.182 35.577,24.474 35.577,25.899 36.928,27.25 37.786,27.25 38.901,28.365 40.261,28.365 41.505,29.609 44.891,29.609 46.932,27.568 50.312,27.568 50.499,27.381 50.499,27.031 v1(50.535,26.995) ; TP49.1@49.75,21.25 49.875,21.375 50.864,21.375 v1(50.989,21.5)
  Bottom Layer w0.25: v1(50.535,26.995) 50.535,22.106 50.989,21.652 v1(50.989,21.5)
NetTP50_1: TP50.1 U4.B4 | length 33.6
  Top Layer w0.152: U4.B4@35.52,21.8 v3(35.657,21.937) ; v2(35.666,23.318) 35.666,24.132 35.882,24.348 35.882,25.773 36.914,26.805 37.772,26.805 38.968,28 40.327,28 41.631,29.305 44.695,29.305 46.737,27.263 49.339,27.263 50.242,26.36 54.015,26.36 54.791,27.136 54.791,30.182 54.701,30.271 54.698,30.271 54.25,30.72 54.25,33.5 54.75,34 TP50.1@55,34
  Layer 2 w0.152: v3(35.657,21.937) 35.666,21.946 v2(35.666,23.318)
NetU8_8: U8.8 U9.8 | length 8.6
  Bottom Layer w0.152: U8.8@72.5,23.05 75.007,23.05 75.081,23.124 77.326,23.124 77.335,23.115 79.58,23.115 80.1,22.595 U9.8@80.9,22.595
SENSE.DOORF: R68.1 TP35.1 U4.J3 | length 37.4
  Top Layer w0.152: v1(33.017,13.176) 33.017,14.017 34.447,15.447 34.447,16.641 34.523,16.717 34.523,17.904 35.12,18.501 U4.J3@35.12,19
  Bottom Layer w0.152: R68.1@29,35.05 29,32.892 31.518,30.374 31.518,27.237 31.37,27.089 31.37,25.689 28.885,23.204 28.885,17.763 29.75,16.898 29.75,13.5 31,12.25 32.091,12.25 v1(33.017,13.176)
  Bottom Layer w0.25: TP35.1@26.9,36.1 27.95,35.05 R68.1@29,35.05
SENSE.DOORV: R66.1 TP36.1 U4.H8 | length 37.2
  Top Layer w0.152: v1(30,33) 30.878,33 30.999,33.121 36.044,33.121 37.234,34.311 38.549,34.311 39,33.86 v1(39,33.75) ; v3(36.983,19.263) U4.H8@37.12,19.4 ; v2(37.955,17.476) 37.952,17.473 37.952,15.548 v1(38,15.5)
  Layer 2 w0.152: v3(36.983,19.263) 36.993,19.254 36.993,19.146 37.85,18.289 37.85,17.621 37.955,17.517 v2(37.955,17.476)
  Bottom Layer w0.152: TP36.1@31.005,33.75 TP36.1@31.054,33.75 TP36.1@31.358,33.75 ; v1@38.874,33.624 v1(39,33.75)
  Bottom Layer w0.25: R66.1@30,35.05 v1(30,33) 30.152,33 30.923,33.771 30.923,33.923 31.044,33.802 TP36.1@31.423,33.802 ; v1(38,15.5) 38.108,15.608 38.108,15.878 38.158,15.928 38.158,27.957 38.502,28.302 38.502,32.752 38.874,33.124 v1@38.874,33.624
SENSE.PWRF_nEN: Q5.G R56.2 R57.2 U4.B8 | length 30.2
  Top Layer w0.152: U4.B8@37.12,21.8 v3(37.257,21.663) ; v2(38.816,22.378) 38.841,22.353 40.395,22.353 40.912,22.869 40.912,22.981 41.063,23.132 41.063,23.563 41.719,24.219 43.738,24.219 44.622,25.104 v1(47.75,25.103) v1(47.75,25.103)
  Layer 2 w0.152: v3(37.257,21.663) 37.26,21.667 37.546,21.667 38.257,22.378 v2(38.816,22.378)
  Bottom Layer w0.152: 41.092,34.038 41.126,34.003 ; R56.2@42.7,33.447 R56.2@42.7,33.497 ; v1@47.671,25.181 v1(47.75,25.103)
  Bottom Layer w0.2: 43.118,27.882 44.348,26.652 46.848,26.652 47.633,25.867 47.633,25.22 v1@47.671,25.181
  Bottom Layer w0.25: R57.2@40.5,35.3 40.55,35.3 40.75,35.1 40.75,34.638 41.073,34.316 41.073,34.057 41.126,34.003 41.198,33.932 41.198,33.157 41.46,32.894 41.863,32.894 42.198,32.894 42.7,33.397 R56.2@42.7,33.447 ; 41.863,32.778 41.863,32.613 41,31.75 41,30 43.118,27.882 ; R56.2@42.7,33.497 42.9,33.697 Q5.G@42.9,34.472
SENSE.PWRV_nEN: Q4.G R47.2 R48.2 U4.A2 | length 34.8
  Top Layer w0.178: v1(34.307,25) 34.244,24.937 34.244,23.926 34.167,23.85 34.167,23.038 34.72,22.486 U4.A2@34.72,22.2 ; v1(34.5,29.25) 35.367,29.25 35.685,29.567 35.933,29.567 36.648,30.283 40.831,30.283 41.11,30.562 45.365,30.562 47.292,28.635 50.657,28.635 51.023,28.269 52.31,28.269 52.556,28.515 54.077,28.515 v1(54.086,28.524)
  Bottom Layer w0.178: v1(34.307,25) 34.404,25.096 34.404,29.154 v1(34.5,29.25) ; Q4.G@55.15,32.947 Q4.G@55.15,32.997
  Bottom Layer w0.2: v1(54.086,28.524) 54.086,28.69 54.411,29.015 54.411,30.61 54.95,31.149 R47.2@54.95,32.046 54.95,32.747 Q4.G@55.15,32.947 ; Q4.G@55.15,32.997 55.75,32.997 R48.2@56.25,33.497
SENSE.VBAT_MEAS: C16.2 R16.2 R18.1 R117.2 TP7.1 | length 14
  Bottom Layer w0.178: R117.2@40,3.3 R117.2@40.05,3.3
  Bottom Layer w0.25: R117.2@40.05,3.3 40.764,2.586 41.938,2.586 42.076,2.448 48.5,2.448 ; TP7.1@48.458,3.5 48.5,3.458 48.5,2.448 ; C16.2@51,3.625 50.865,3.49 50.69,3.49 49.95,2.75 49.892,2.75 49.816,2.674 49.25,2.674 49.024,2.448 48.5,2.448 ; C16.2@51,3.625 R18.1@52.05,3.624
